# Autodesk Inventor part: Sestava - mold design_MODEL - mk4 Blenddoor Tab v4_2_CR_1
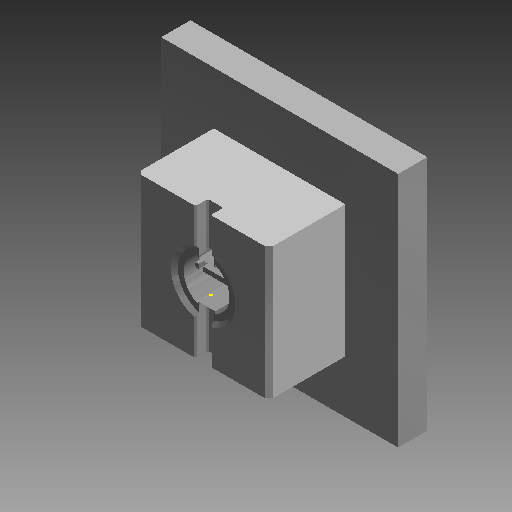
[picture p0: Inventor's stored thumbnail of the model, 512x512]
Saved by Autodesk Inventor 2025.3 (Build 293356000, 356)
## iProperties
Part Number: Sestava - mold design_MODEL - mk4 Blenddoor Tab v4_2_CR_1
Material: Generický
Document SubType Name: Modelování
Designer: Patrik
Density: 1 g/cm^3
Appearance: Výchozí
Description: Tvárnice
Author: Patrik
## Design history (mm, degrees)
node "Sestava - mold design_MODEL - mk4 Blenddoor Tab v4_2_CR_Base"
sketch "Náčrt2"
  geometry: 1 further point
  constraints: 1 other
node "Objemová tělesa"
node "Povrchová tělesa"
feature "Těleso7::Sestava - mold design_MODEL - mk4 Blenddoor Tab v4_"
tag "Prvek štítků3"
node "Těleso7"
feature "Sestava - mold design_MODEL - mk4 Blenddoor Tab v4_2_CR_Base"
